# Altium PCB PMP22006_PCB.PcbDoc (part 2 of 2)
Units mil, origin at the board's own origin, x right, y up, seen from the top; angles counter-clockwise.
Board outline 2500 x 1522 mil, 4 copper layers (Top Layer, Signal Layer 1, Signal Layer 2, Bottom Layer), stack 186.034 mil thick; 52 components, 32 nets, 135 pads, 25 vias.
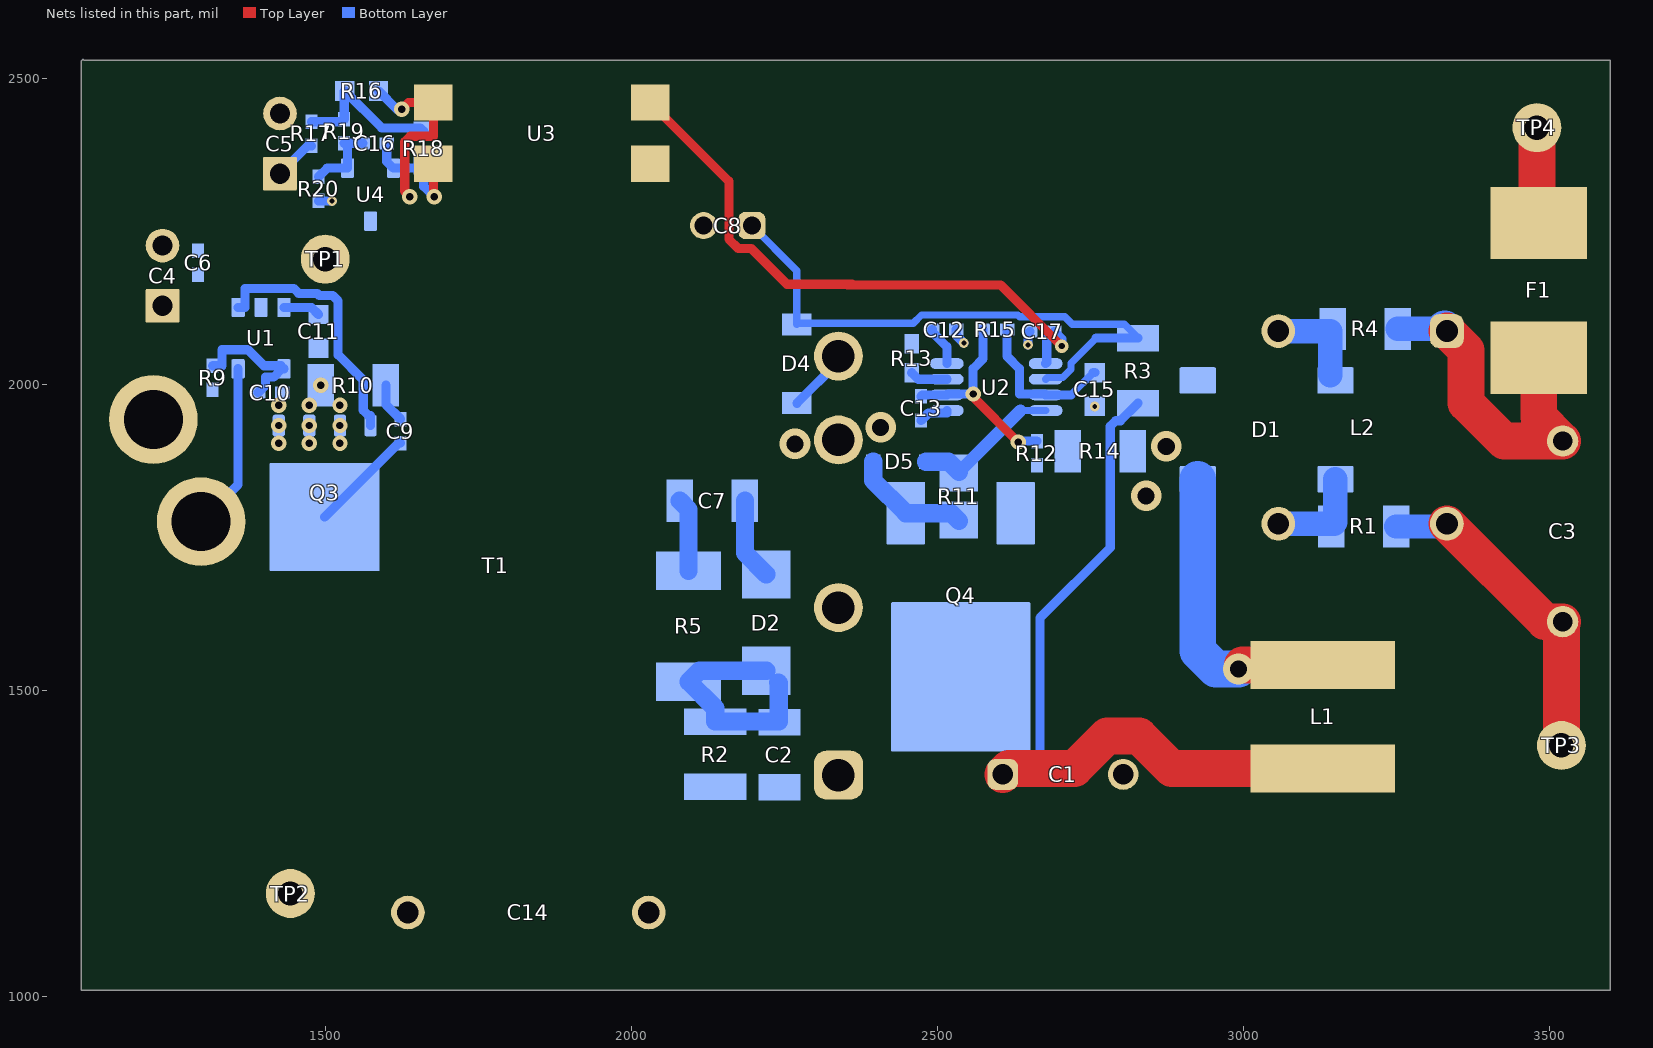
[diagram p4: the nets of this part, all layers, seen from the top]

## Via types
v1: diameter 25, hole 12, Top Layer to Bottom Layer, 15 vias
v2: diameter 50, hole 28, Top Layer to Bottom Layer, 5 vias
v3: diameter 16, hole 8, Top Layer to Bottom Layer, 4 vias
v4: diameter 22, hole 10, Top Layer to Bottom Layer, 1 vias

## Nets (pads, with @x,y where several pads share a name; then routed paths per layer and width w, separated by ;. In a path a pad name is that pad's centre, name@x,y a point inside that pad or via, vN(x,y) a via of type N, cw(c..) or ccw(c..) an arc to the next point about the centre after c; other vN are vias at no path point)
GND: C4.2 C5.2 C6.2 C10.2 C11.2 C14.1 Q3.1 Q3.2 Q3.3 R10.2 R20.1 TP2.1 U1.2 U4.3 | length 22
  Bottom Layer w15: R20.1@1488,2300.32 v3(1510,2300.32)
  other v1: 1423,1904 1473,1904 1523,1904 1423,1933.04 1473,1933.04 1523,1933.04 1423,1966 1473,1966 1523,1966 1491.85,1999
LINE: F1.2 TP4.1 | length 157
  Top Layer w60: TP4.1@3480,2420 3480,2267.24 F1.2@3483,2264.24
NetC2_2: C2.2 D2.1 R2.1 R5.2 | length 385.9
  Bottom Layer w30: D2.1@2220,1532.26 2110.81,1532.26 R5.2@2093,1514.45 2136.57,1470.87 R2.1@2136.57,1449.15 2240.57,1449.15 2240.57,1511.69 D2.1@2239.41,1512.85
NetC3_2: C3.2 F1.1 L2.1 R4.1 | length 548.6
  Top Layer w60: L2.1@3332.8,2087.48 3364,2056.28 3364,1970 3426.36,1907.64 C3.2@3522,1907.64 3483,1946.64 F1.1@3483,2043.76
  Bottom Layer w40: R4.1@3252.15,2091 L2.1@3329.28,2091
  Bottom Layer w60: L2.1@3329.28,2091 L2.1@3332.8,2087.48
NetC7_1: C7.1 R5.1 | length 120.3
  Bottom Layer w30: C7.1@2078.85,1810 2093,1795.85 R5.1@2093,1695.55
NetC7_2: C7.2 D2.2 Q4.4 T1.3 | length 134.3
  Bottom Layer w30: C7.2@2185.15,1810 2185.15,1724.59 D2.2@2219.74,1690
NetC8_1: C8.1 D4.1 R3.1 U2.2 | length 956.2
  Bottom Layer w12: C8.1@2196.37,2260 2270,2186.37 D4.1@2270,2100.33 ; D4.1@2270,2098.47 D4.1@2270,2100.33 ; U2.2@2676.71,2008.8 2679.57,2011.65 2704.83,2011.65 2718.14,2024.97 2718.14,2034.92 2759.37,2076.15 ; R3.1@2828,2076.15 2805.68,2098.47 2720.49,2098.47 2708.24,2110.72 2634.24,2110.72 2631.24,2113.72 2473.76,2113.72 2460.38,2100.33 D4.1@2270,2100.33
  Bottom Layer w15: 2759.37,2076.15 R3.1@2828,2076.15
NetC9_1: C9.1 Q3.5 Q3.6 Q3.7 Q3.8 Q3.9@1498,1783.43 T1.B U1.5 | length 449
  Bottom Layer w15: T1.B@1296,1776 1356.6,1836.6 U1.5@1356.6,2025.8 ; Q3.9@1498,1783.43 1618.88,1904.31 C9.1@1622,1904.32
NetC9_2: C9.2 R10.1 | length 65.2
  Bottom Layer w15: R10.1@1598.15,1999 1598.15,1967.54 C9.2@1622,1943.69
NetC10_1: C10.1 R9.2 U1.4 | length 221.3
  Bottom Layer w15: R9.2@1315,2030.69 1330.4,2030.69 1330.4,2056.93 1372.65,2056.93 1398.89,2030.69 1426.52,2030.69 U1.4@1431.4,2025.8 1428.12,2025.8 1414.53,2012.22 1401.5,2012.22 1401.5,1999.19 C10.1@1389.32,1987
NetC11_1: C11.1 U1.3 | length 61.4
  Bottom Layer w15: U1.3@1431.4,2126.2 1476.36,2126.2 C11.1@1488,2114.56
NetC12_2: C12.2 U2.8 | length 65.5
  Bottom Layer w15: C12.2@2491.31,2090 2491.31,2085.97 2515.29,2062 U2.8@2515.29,2034.39
NetC13_2: C13.2 R12.2 R15.1 U2.6 | length 339.1
  Top Layer w15: v1(2558.22,1984.56) 2558.22,1979.78 v1(2632,1906)
  Bottom Layer w15: C13.2@2473,1980.69 2475.52,1983.2 U2.6@2515.29,1983.2 2516.65,1984.56 v1(2558.22,1984.56) 2558.22,2026.14 2574.32,2042.23 R15.1@2574.32,2090 ; v1(2632,1906) 2633.69,1907.69 R12.2@2662.32,1907.69
NetC15_1: C15.1 R15.2 U2.3 | length 252.6
  Bottom Layer w12: 2718.2,1983.2 C15.1@2754.56,2019.56
  Bottom Layer w15: R15.2@2613.69,2090 2613.69,2046.23 2633.78,2026.14 2633.78,1984.56 2675.35,1984.56 U2.3@2676.71,1983.2 2718.2,1983.2 ; C15.1@2754.56,2019.56 C15.1@2757,2019.56
NetC16_1: C16.1 R18.2 U3.2 U4.2 | length 210.3
  Top Layer w15: U3.2@1675.83,2361 1675.83,2308.17 v1(1677,2307)
  Bottom Layer w15: C16.1@1599.68,2394.47 1599.68,2364.58 U4.2@1610.4,2353.87 1654.83,2353.87 R18.2@1660,2359.03 1660,2324 v1(1677,2307)
NetC16_2: C16.2 R19.1 R20.2 U4.1 | length 126.7
  Bottom Layer w15: R20.2@1488,2339.69 1502.18,2353.87 U4.1@1535.6,2353.87 1535.6,2388.87 R19.1@1530,2394.47 C16.2@1560.31,2394.47
NetC17_2: C17.2 U2.1 U3.4 | length 970
  Top Layer w15: U3.4@2030.17,2461 2158.85,2332.32 2158.85,2237.82 2174.19,2222.48 2195.52,2222.48 2254,2164 2360,2164 ; 2353,2163 2602.93,2163 v4(2703,2062.93)
  Bottom Layer w15: U2.1@2676.71,2034.39 2678.5,2036.18 2678.5,2074.81 ; C17.2@2690.69,2087 2703,2074.69 v4(2703,2062.93)
NetD1_1: D1.1 L1.1 | length 500.4
  Top Layer w40: v2(2992,1535) v2@2998.65,1541.65
  Top Layer w60: v2@2998.65,1541.65 L1.1@3130,1541.65
  Bottom Layer w60: D1.1@2925.4,1845.29 2925.4,1564.4 2954.8,1535 v2(2992,1535)
NetD1_2: D1.2 L2.3 R1.2 | length 164.9
  Bottom Layer w40: L2.3@3057.2,1772.52 3148.37,1772.52 3150.6,1774.75 D1.2@3150.6,1845.29
NetD1_3: D1.3 L2.2 R4.2 | length 157.6
  Bottom Layer w40: L2.2@3057.2,2087.48 3142.33,2087.48 D1.3@3142.33,2014.98
NetD4_2: D4.2 T1.6 | length 105.1
  Bottom Layer w15: D4.2@2270,1969.53 2338,2037.53 T1.6@2338,2046.5
NetD5_1: D5.1 R11.2 U2.4 | length 244.1
  Bottom Layer w12: 2635.61,1957.61 U2.4@2676.71,1957.61
  Bottom Layer w20: R11.2@2535,1857 2635.61,1957.61
  Bottom Layer w30: D5.1@2481.31,1874 2518,1874 R11.2@2535,1857
NetD5_2: D5.2 Q4.1 R11.1 | length 198.4
  Bottom Layer w30: D5.2@2394.69,1874 2394.69,1843.4 Q4.1@2448.24,1789.86 2522.14,1789.86 R11.1@2535,1777
NetQ3_4: Q3.4 U1.1 | length 430.4
  Bottom Layer w15: U1.1@1356.6,2126.2 1367.8,2126.2 1367.8,2157.32 1447.45,2157.32 1455.7,2149.07 1485.84,2149.07 1489.23,2145.68 1511.1,2145.68 1520.11,2136.68 1520.11,2048.59 1561.12,2007.57 1561.12,1958.18 1570.13,1949.18 1573,1949.18 Q3.4@1573,1933.04
NetQ4_3: Q4.3 R12.1 R14.1
NetR13_2: R13.2 U2.7 | length 61.7
  Bottom Layer w15: R13.2@2458,2019.38 2468.58,2008.8 U2.7@2515.29,2008.8
NetR16_1: R16.1 U3.1 | length 311.5
  Top Layer w15: v1(1624,2450) 1635,2461 U3.1@1675.83,2461 1675.83,2405.9 1637.97,2405.9 1628.96,2396.9 1628.96,2316.1 1637,2308.06 v1(1637,2307.03) v1@1637,2306
  Bottom Layer w15: R16.1@1586.19,2480 1616.19,2450 v1(1624,2450) ; v1@1633.47,2310.56 v1(1637,2307.03)
NetR16_2: R16.2 R17.1 R18.1 R19.2 | length 258.2
  Bottom Layer w15: R17.1@1476.36,2429.68 1525.85,2429.68 R19.2@1530,2433.84 1530,2478.93 R16.2@1531.07,2480 1591.39,2419.68 1654.47,2419.68 R18.1@1660,2414.15
NTRL: C3.1 L2.4 R1.1 TP3.1 | length 543.3
  Top Layer w60: L2.4@3332.8,1772.52 3492.95,1612.36 C3.1@3522,1612.36 3520,1610.36 TP3.1@3520,1410
  Bottom Layer w40: R1.1@3250.15,1768 3328.28,1768 L2.4@3332.8,1772.52
PGND: C1.2 C8.2 C12.1 C13.1 C14.2 C15.2 C17.1 D1.4 R13.1 R14.2 T1.5 U2.5 U3.3 | length 101.9
  Bottom Layer w15: C13.1@2473,1941.32 2485.19,1953.5 2515.29,1953.5 U2.5@2515.29,1957.61 ; C12.1@2530.68,2090 2530.68,2080.32 v3(2543,2068) ; v3(2648,2065) 2648,2083.68 C17.1@2651.32,2087
  other v2: 2841,1818 2874,1899 2267,1903 2407,1930
  other v3: 2757,1963.95
VIN: C1.1 C2.1 L1.2 R2.2 R3.2 T1.1 | length 1297.7
  Top Layer w60: C1.1@2606.57,1362.67 2616.26,1372.35 2724.05,1372.35 2777.34,1425.64 2829.51,1425.64 2882.8,1372.35 L1.2@3130,1372.35
  Bottom Layer w15: C1.1@2606.57,1362.67 2628.63,1384.72 2667.55,1384.72 2667.55,1618.55 2782.44,1733.44 2782.44,1931.82 2791.44,1940.82 2798.97,1940.82 R3.2@2828,1969.85
VOUT: C4.1 C5.1 C6.1 R9.1 R17.2 T1.A TP1.1 | length 82.5
  Bottom Layer w15: C5.1@1437.29,2344.79 C5.1@1425,2344.79 1470.53,2390.31 R17.2@1476.36,2390.31
pads on no net: Q3.9@1440.91,1767.88 Q3.9@1440.91,1837.96 Q3.9@1498,1767.88 Q3.9@1498,1801.35 Q3.9@1498,1837.96 Q3.9@1555.09,1767.88 Q3.9@1555.09,1837.96

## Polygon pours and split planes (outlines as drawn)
VIN on Bottom Layer "BOTTOM_LAYER_VIN_P000" (solid, remove dead copper, pour order 0): 2054,1236 2054,1580.46 2384,1580.46 2384,1375 2398,1361 2404,1367 2530,1367 2530,1401.94 2538.06,1410 2733,1410 2733,1312 2702,1281 2387,1281 2387,1236 2384,1233 2382.39,1234.61 2043.23,1234.61
NetC7_2 on Bottom Layer "BOTTOM_LAYER_NETC7_2_P002" (solid, remove dead copper, pour order 2): 2405,1391 2653.34,1391 2662.3,1399.96 2662.3,1715.06 2283.06,1715.06 2281,1713 2264,1730 2264,1758 2171,1758 2163,1750 2163,1590 2399.67,1590 2401.67,1592 2406,1587.67 2406,1393
NetQ4_3 on Bottom Layer "BOTTOM_LAYER_NETQ4_3_P004" (solid, remove dead copper, pour order 4): 2590,1727 2590,1855 2585,1860 2636,1860 2636,1884 2642,1890 2682,1890 2682,1936 2684,1938 2761,1938 2761,1728 2762,1727 2761,1726 2591,1726
PGND on Bottom Layer "BOTTOM_LAYER_PGND_P012" (solid, remove dead copper, pour order 12): 2059,1295 2961,1295 2959,1297 2959,2163 2332,2163 2268,2227 2233.66,2305.66 2191,2334 2114,2411 1951,2411 1951,1075 1954,1072 2069,1072 2069,1294 2066,1297
NetC9_1 on Bottom Layer "BOTTOM_LAYER_NETC9_1_P006" (solid, remove dead copper, pour order 6): 1600,1680 1245,1680 1245,1706 1247,1708 1185,1770 1185,1844 1210,1869 1353,1869 1361,1877 1603,1877 1603,1681 1601,1679
VOUT on Bottom Layer "BOTTOM_LAYER_VOUT_P008" (solid, remove dead copper, pour order 8): 1112,1867 1112,2176 1108,2180 1234.89,2279.04 1338,2349 1358,2369 1566,2369 1566,2130 1542,2106 1336,2106 1336,1872 1331,1867
GND on Bottom Layer "BOTTOM_LAYER_GND_P024" (solid, remove dead copper, pour order 24): 1286,2508 1764.61,2508 1767,2510.39 1767,1009 1335.56,1009 1326.56,1000 1102,1000 1102,2527 1120,2509 1287,2509
VOUT on Top Layer "TOP_LAYER_VOUT_P010" (solid, remove dead copper, pour order 10): 1112,1867 1112,2176 1108,2180 1234.89,2279.04 1338,2349 1358,2369 1566,2369 1566,2130 1542,2106 1336,2106 1336,1872 1331,1867
PGND on Top Layer "TOP_LAYER_PGND_P020" (solid, remove dead copper, pour order 20): 2052,1311 2959,1311 2959,2165 2330,2165 2268,2227 2268,2334 2191,2334 2114,2411 1951,2411 1951,1075 1954,1072 2069,1072 2069,1294
GND on Top Layer "TOP_LAYER_GND_P022" (solid, remove dead copper, pour order 22): 1675,1033 1675,1192 1542,1192 1542,2203 1726,2203 1726,2524 1728,2526 1722,2532 1103,2532 1103,1009 1104,1010 1676,1010 1676,1033
PGND on Signal Layer 1 "SIGNAL_LAYER_1_PGND_P014" (solid, remove dead copper, pour order 14): 2059,1295 2961,1295 2959,1297 2959,2163 2332,2163 2268,2227 2233.66,2305.66 2191,2334 2114,2411 1951,2411 1951,1075 1954,1072 2069,1072 2069,1294 2066,1297
GND on Signal Layer 1 "SIGNAL_LAYER_1_GND_P026" (solid, remove dead copper, pour order 26): 1286,2508 1764.61,2508 1767,2510.39 1767,1009 1335.56,1009 1326.56,1000 1102,1000 1102,2527 1120,2509 1287,2509
PGND on Signal Layer 2 "SIGNAL_LAYER_2_PGND_P018" (solid, remove dead copper, pour order 18): 2059,1295 2961,1295 2959,1297 2959,2161 2334,2161 2268,2227 2233.66,2305.66 2191,2334 2114,2411 1951,2411 1951,1075 1954,1072 2069,1072 2069,1294 2066,1297
GND on Signal Layer 2 "SIGNAL_LAYER_2_GND_P028" (solid, remove dead copper, pour order 28): 1286,2508 1764.61,2508 1767,2510.39 1767,1009 1335.56,1009 1326.56,1000 1102,1000 1102,2527 1120,2509 1287,2509

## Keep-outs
Keep-Out Layer:
  text ".Layer_Name" at 577,-858.49 h60

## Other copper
Top Layer:
  text ".Layer_Name" at 577,-858.49 h60
Bottom Layer:
  text ".Layer_Name" at 577,-858.49 h60

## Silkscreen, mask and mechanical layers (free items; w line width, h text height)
Top Overlay:
  text "'.PRJ_Number'.PCB_Rev-" at 2578,1181 h108.27
  text ".Layer_Name" at 577,-858.49 h60
Bottom Overlay:
  text ".Layer_Name" at 577,-858.49 h60
Top Paste:
  text ".Layer_Name" at 577,-858.49 h60
Bottom Paste:
  text ".Layer_Name" at 577,-858.49 h60
Top Solder:
  text ".Layer_Name" at 577,-858.49 h60
  text ".Layer_Name" at 577,-858.49 h60
Bottom Solder:
  text ".Layer_Name" at 577,-858.49 h60
Drill Guide:
  text ".Layer_Name" at 577,-858.49 h60
M1 Board Outline:
  text ".Layer_Name" at 577,-858.49 h60
M2 Board Dimensions:
  rectangle: 125,-400 500,-275
  rectangle: 0,-275 125,-150
  lines w7: 0,-275 1000,-275 ; 125,-400 125,-150 ; 250,-400 250,-150 ; 500,-400 500,-150 ; 750,-400 750,-150 ; 0,-400 0,-150 1000,-150 1000,-400 0,-400
  text ".Layer_Name" at 577,-858.49 h60
M3 3D STEP Top:
  text ".Layer_Name" at 577,-858.49 h60
M4 3D STEP Bottom:
  text ".Layer_Name" at 577,-858.49 h60
M5 Assembly Top:
  lines w10: -292,-930.17 6308,-930.17 ; -292,-726.83 6310,-726.83 ; -292,-523.5 -292,-1133.5 3713,-1133.5 6310,-1133.5 6310,-523.5 -291.5,-523.5 -291.5,-1133.5 1284,-1133.5 ; 2173,-1133.5 2173,-523.5 ; 3440,-726.83 3440,-523.5 ; 4280,-726.83 4280,-523.5 ; 4902,-1140 4902,-937.17
  text "COMPONENTS MARKED 'DNP' SHOULD NOT BE POPULATED." at 1153.5,-318.5 h60
  text "ASSEMBLY VARIANT:" at 1153,-434 h60
  text ".VariantName" at 2189,-434 h60
  text "PCB VIEWED FROM TOP SIDE" at -228.5,-655.67 h60
  text "BOARD #:" at 2248,-655.67 h60
  text ".PRJ_Number" at 2793.5,-655.67 h60
  text "REV:" at 3638,-655.67 h60
  text ".PCB_Rev" at 3929.5,-655.67 h60
  text "SVN REV:" at 4476,-655.67 h60
  text ".VersionControl_RevNumber" at 4982,-655.67 h60
  text "TID #:" at 2248,-859 h60
  text ".TID" at 2793.5,-859 h60
  text "PLOT NAME =" at -228.5,-1064.34 h60
  text ".plot_File_Name" at 577,-1064.34 h60
  text "GENERATED    :" at 2250,-1064.34 h60
  text ".Print_Date" at 3119.5,-1064.34 h60
  text ".Print_Time" at 3848.5,-1064.34 h60
  text "TEXAS INSTRUMENTS" at 5113,-1064.34 h60
M6 Assembly Bottom:
  lines w10: -292.5,-727.33 6309.5,-727.33 ; -290.5,-930.67 6309.5,-930.67 ; 1115.5,-1140.5 1115.5,-937.67 ; 1737.5,-727.33 1737.5,-524 ; 2577.5,-727.33 2577.5,-524 ; 3844.5,-1134 3844.5,-524 ; 4733.5,-1134 6309,-1134 6309,-524 -292.5,-524 -292.5,-1134 2304.5,-1134 6309.5,-1134 6309.5,-524
  text "COMPONENTS MARKED 'DNP' SHOULD NOT BE POPULATED." at 6102,-318 h60
  text ".VariantName" at 5058,-434 h60
  text "ASSEMBLY VARIANT:" at 6097,-434 h60
  text ".VersionControl_RevNumber" at 1035.5,-656.17 h60
  text "SVN REV:" at 1541.5,-656.17 h60
  text ".PCB_Rev" at 2088,-656.17 h60
  text "REV:" at 2379.5,-656.17 h60
  text ".PRJ_Number" at 3224,-656.17 h60
  text "BOARD #:" at 3769.5,-656.17 h60
  text "PCB VIEWED FROM BOTTOM SIDE" at 6246,-656.17 h60
  text ".TID" at 3224,-859.5 h60
  text "TID #:" at 3769.5,-859.5 h60
  text "TEXAS INSTRUMENTS" at 904.5,-1064.84 h60
  text ".Print_Time" at 2169,-1064.84 h60
  text ".Print_Date" at 2898,-1064.84 h60
  text "GENERATED    :" at 3767.5,-1064.84 h60
  text ".plot_File_Name" at 5440.5,-1064.84 h60
  text "PLOT NAME =" at 6246,-1064.84 h60
M9 Title Sheet:
  drawing of 57 lines, arcs and shapes, not listed
  text "1" at 739.84,8036.5 h70
  text "2" at 3235.5,8036.5 h70
  text "3" at 5724.84,8036.5 h70
  text "4" at 8231.51,8036.5 h70
  text "5" at 10730.5,8036.5 h70
  text "6" at 13235.5,8036.5 h70
  text "A" at -416.5,6893.5 h70
  text "A" at 14383.5,6893.5 h70
  text "B" at -416.5,4513.5 h70
  text "B" at 14383.5,4513.5 h70
  text "C" at -416.5,2138.5 h70
  text "C" at 14383.5,2138.5 h70
  text "PROJECT TITLE:" at 11343.5,277.5 h45
  text ".PRJ_Title" at 11393.5,144.17 h70
  text "DESIGNED FOR:" at 11343.5,-23.5 h45
  text ".PRJ_Customer" at 11393.5,-163.5 h70
  text "D" at -416.5,-231.5 h70
  text "D" at 14383.5,-231.5 h70
  text "FILE NAME:" at 11343.5,-323.5 h45
  text ".PCB_File_Name_No_Path" at 11393.5,-443.5 h70
  text "Texas Instruments (TI) and/or its licensors do not warrant the accuracy or completeness of this specification" at 6374,-605.34 h45
  text "ENGINEER:" at 11343.5,-613.5 h45
  text "LAYOUT BY:" at 12848.5,-613.5 h45
  text "or any information contained therein. TI and/or its licensors do not warrant that this design will meet" at 6329.01,-718 h45
  text ".PRJ_Engineer" at 11393.5,-768.49 h70
  text ".PCB_Layout" at 12899,-768.49 h70
  text "the specifications, will be suitable for your application or fit for any particular purpose, or will operate in" at 6329.01,-830.67 h45
  text ".Layer_Name" at 577,-858.49 h60
  text "ALTIUM DESIGNER VERSION:" at 12848.5,-923.5 h45
  text "an implementation. TI and/or its licensors do not warrant that the design is production worthy. You should" at 6329.01,-943.33 h45
  text "completely validate and test your design implementation to confirm the system functionality for your application." at 6374,-1056 h45
  text ".print_Scale" at 11393.5,-1056.83 h70
  text ".Application_BuildNumber" at 12899,-1056.83 h70
  text "1" at 739.84,-1263.5 h70
  text "2" at 3235.5,-1263.5 h70
  text "3" at 5724.84,-1263.5 h70
  text "4" at 8231.51,-1263.5 h70
  text "5" at 10730.5,-1263.5 h70
  text "6" at 13235.5,-1263.5 h70
M10 Fab Notes:
  drawing of 173 lines, arcs and shapes, not listed
  text "DESIGN INFORMATION" at 12378.02,6201 h60
  text "MIN. TRACK WIDTH:" at 11733.46,6021 h60
  text "8" at 12829.7,6021 h60
  text "MIL" at 12984.46,6021 h60
  text "MIN. CLEARANCE:" at 11733.46,5889 h60
  text "0.2" at 12769.7,5889 h60
  text "mm" at 12984.46,5889 h60
  text "MIN. VIA PAD SIZE:" at 11733.46,5757 h60
  text "24" at 12799.71,5757 h60
  text "MIL" at 12984.46,5757 h60
  text "0.05mm (2MIL)" at 12428.46,5615.29 h60
  text "MINIMUM ANNULAR RING" at 11404.23,5611 h60
  text "EXTERNAL" at 13136.46,5611 h60
  text "PER" at 11604.23,5493 h60
  text "IPC-D-275 CLASS 2 LEVEL C" at 11824.23,5493 h60
  text "MIL, HOLES" at 13312.46,5380.71 h60
  text "+/-" at 12920,5380 h60
  text "+/-" at 13774,5380 h60
  text "REGISTRATION TOLERANCES:" at 11404.23,5375 h60
  text "METAL" at 12604,5375 h60
  text "5" at 13180.2,5375 h60
  text "3" at 14013.2,5375 h60
  text "MIL" at 14129.46,5375 h60
  text "+/-" at 13774,5262 h60
  text "HOLE SIZE TOLERANCE (UNLESS OTHERWISE SPECIFIED):" at 11404.23,5257 h60
  text "3" at 14013.2,5257 h60
  text "MIL" at 14129.46,5257 h60
  text "MATERIAL:" at 11329.46,5047.54 h60
  text "FR-4 High Tg" at 12315.9,4907.21 h60
  text "FR-408" at 11750.46,4898.64 h60
  text "OTHER" at 13238.46,4898.64 h60
  text "X" at 12161,4895 h60
  text "62 MIL (1.6mm) +/-10%" at 12070.56,4735.92 h60
  text "THICKNESS:" at 11404.23,4731.64 h60
  text "X" at 11942.4,4731.64 h60
  text "OTHER" at 13355.46,4731.64 h60
  text "TOLERANCE:" at 11404.23,4573.64 h60
  text "X" at 12243.53,4573.64 h60
  text "ANSI IPC-6012 TYPE 3 CLASS 2" at 12430.48,4573.64 h60
  text "OTHER +/-" at 12430.46,4417.64 h60
  text "BOW & TWIST:" at 11404.23,4260.64 h60
  text "X" at 12243.53,4260.64 h60
  text "ANSI IPC-6012 TYPE 3 CLASS 2" at 12430.48,4260.64 h60
  text "OTHER +/-" at 12430.46,4102.13 h60
  text "DRILLING:" at 11329.46,3963.64 h60
  text "REFERENCE:" at 11404.23,3846.64 h60
  text "X" at 12052.46,3846.64 h60
  text "AS SHOWN" at 12239.46,3846.64 h60
  text "X" at 12953.46,3846.64 h60
  text "NC_DRILL FILES" at 13090.46,3846.64 h60
  text "PTH COPPER THICKNESS:" at 11404.23,3688.64 h60
  text "X" at 12534.46,3688.64 h60
  text "20-30 um" at 12671.46,3688.64 h60
  text "OTHER" at 13388.46,3688.64 h60
  text "BOARD FINISH:" at 11329.46,3529.64 h60
  text "SILKSCREEN:" at 11484.68,3411.64 h60
  text "X" at 12433.46,3411.64 h60
  text "TOP" at 12559.46,3411.64 h60
  text "X" at 12943.46,3411.64 h60
  text "BOTTOM" at 13070.46,3411.64 h60
  text "SILKSCREEN COLOR:" at 11484.68,3244.64 h60
  text "X" at 12432.42,3244.64 h60
  text "WHITE" at 12559.46,3244.64 h60
  text "OTHER" at 13070.46,3244.64 h60
  text "X" at 12563.42,3085.44 h60
  text "GREEN" at 12690.46,3085.44 h60
  text "OTHER" at 13308.46,3085.44 h60
  text "SOLDER RESIST COLOR:" at 11484.68,3074.64 h60
  text "X" at 12563.42,2915.44 h60
  text "MATTE" at 12690.46,2915.44 h60
  text "SEMI-GLOSS" at 13308,2914.8 h60
  text "IMMERSION GOLD (ENIG)" at 12390.46,2726.92 h60
  text "ENEPIG" at 13728,2723.64 h60
  text "SURFACE FINISH:" at 11329.46,2722.64 h60
  text "X" at 12203.51,2722.64 h60
  text "IMM. TIN/SILVER OR EQUIV" at 11659,2565.64 h60
  text "OTHER" at 13090.46,2565.64 h60
  text "ARRAY/PANEL:" at 11329.46,2386.64 h60
  text "CUT AND TRIM PER M1 BOARD OUTLINE" at 12390.46,2382.35 h60
  text "N.C. ROUTE" at 12390.46,2230.64 h60
  text "X" at 13069.46,2230.64 h60
  text "V. SCORE" at 13256.46,2230.64 h60
  text "CERTIFICATION:" at 11329.46,2093.64 h60
  text "MATERIALS AND WORKMANSHIP FOR ALL PCBS" at 12054.46,2093.64 h60
  text "TO MEET OR EXCEED THE REQUIREMENTS OF:" at 12054.46,1995.64 h60
  text "X" at 11680.96,1859.13 h60
  text "ANSI IPC-A-600F CLASS ->" at 11819.96,1859.13 h60
  text "X" at 13459.02,1859.13 h60
  text "2" at 13577.96,1859.14 h60
  text "1" at 13262.96,1857.64 h60
  text "3" at 13931.96,1857.64 h60
  text "X" at 12495.02,1699.64 h60
  text "RoHS" at 12631.96,1699.64 h60
  text "OTHER" at 13276.36,1699.64 h60
  text "PER ORDER" at 13673.42,1699.64 h60
  text "ALL BOARDS MUST MEET OR EXCEED UL94-V0 REQUIREMENTS." at 11357,1534 h60
  text "PCB MUST BEAR THE UL94V-0 UL REGISTERED MATERIAL ID NUMBER" at 11357,1414 h60
  text "ADDITIONAL REQUIREMENTS:" at 11329.46,1240.64 h60
  text "MICROSECTION:" at 11404.23,1125.64 h60
  text "YES" at 12309.96,1125.64 h60
  text "REQUIRED" at 13171.46,969.49 h60
  text "BARE BOARD ELEC. TEST:" at 11404.23,966.64 h60
  text "NONE" at 12709.96,966.64 h60
  text "X" at 13044.46,966.64 h60
  text "PER ORDER" at 13763.46,966.64 h60
  text ".Layer_Name" at 577,-858.49 h60
M11 Gerber Information:
  lines w10: -292,-930.17 6308,-930.17 ; -292,-726.83 6310,-726.83 ; -292,-523.5 -292,-1133.5 3713,-1133.5 6310,-1133.5 6310,-523.5 -291.5,-523.5 -291.5,-1133.5 1284,-1133.5 ; 2173,-1133.5 2173,-523.5 ; 3440,-726.83 3440,-523.5 ; 4280,-726.83 4280,-523.5 ; 4902,-1140 4902,-937.17
  text "ALL ARTWORK VIEWED FROM TOP SIDE" at -228.5,-655.67 h60
  text "BOARD #:" at 2248,-655.67 h60
  text ".PRJ_Number" at 2793.5,-655.67 h60
  text "REV:" at 3638,-655.67 h60
  text ".PCB_Rev" at 3929.5,-655.67 h60
  text "SVN REV:" at 4476,-655.67 h60
  text ".VersionControl_RevNumber" at 4982,-655.67 h60
  text "LAYER NAME =" at -228.5,-858.49 h60
  text "TID #:" at 2248,-859 h60
  text ".TID" at 2793.5,-859 h60
  text "PLOT NAME =" at -228.5,-1064.34 h60
  text ".plot_File_Name" at 577,-1064.34 h60
  text "GENERATED    :" at 2250,-1064.34 h60
  text ".Print_Date" at 3119.5,-1064.34 h60
  text ".Print_Time" at 3848.5,-1064.34 h60
  text "TEXAS INSTRUMENTS" at 5113,-1064.34 h60
M12 Stackup:
  drawing of 527 lines, arcs and shapes, not listed
  text "Layer" at 9797.84,7785 h60
  text "Name" at 10207.76,7785 h60
  text "Material" at 11147.5,7785 h60
  text "Thickness" at 12007.26,7785 h60
  text "Constant" at 12657.1,7785 h60
  text "Board Layer Stack" at 13226.96,7785 h60
  text "Board Layer Stack" at 14346.64,7785 h60
  text "1" at 9797.84,7665 h60
  text "Top Overlay" at 10207.76,7665 h60
  text "2" at 9797.84,7545 h60
  text "Top Solder" at 10207.76,7545 h60
  text "Solder Resist" at 11147.5,7545 h60
  text "0.40mil" at 12007.26,7545 h60
  text "3.5" at 12657.1,7545 h60
  text "3" at 9797.84,7425 h60
  text "Top Layer" at 10207.76,7425 h60
  text "Copper" at 11147.5,7425 h60
  text "2.80mil" at 12007.26,7425 h60
  text "4" at 9797.84,7305 h60
  text "Dielectric1" at 10207.76,7305 h60
  text "FR-4" at 11147.5,7305 h60
  text "59.20mil" at 12007.26,7305 h60
  text "4.8" at 12657.1,7305 h60
  text "5" at 9797.84,7185 h60
  text "Signal Layer 1" at 10207.76,7185 h60
  text "Copper" at 11147.5,7185 h60
  text "1.42mil" at 12007.26,7185 h60
  text "6" at 9797.84,7065 h60
  text "Dielectric 2" at 10207.76,7065 h60
  text "FR-4" at 11147.5,7065 h60
  text "59.20mil" at 12007.26,7065 h60
  text "4.8" at 12657.1,7065 h60
  text "7" at 9797.84,6945 h60
  text "Signal Layer 2" at 10207.76,6945 h60
  text "Copper" at 11147.5,6945 h60
  text "1.42mil" at 12007.26,6945 h60
  text "8" at 9797.84,6825 h60
  text "Dielectric 3" at 10207.76,6825 h60
  text "FR-4" at 11147.5,6825 h60
  text "59.20mil" at 12007.26,6825 h60
  text "4.8" at 12657.1,6825 h60
  text "9" at 9797.84,6705 h60
  text "Bottom Layer" at 10207.76,6705 h60
  text "Copper" at 11147.5,6705 h60
  text "2.80mil" at 12007.26,6705 h60
  text "10" at 9797.84,6585 h60
  text "Bottom Solder" at 10207.76,6585 h60
  text "Solder Resist" at 11147.5,6585 h60
  text "0.40mil" at 12007.26,6585 h60
  text "3.5" at 12657.1,6585 h60
  text "11" at 9797.84,6465 h60
  text "Bottom Overlay" at 10207.76,6465 h60
  text ".Layer_Name" at 577,-858.49 h60
M13 Component Bodies Top:
  text ".Layer_Name" at 577,-858.49 h60
M14 Component Bodies Bottom:
  text ".Layer_Name" at 577,-858.49 h60
M15 Courtyards Top:
  text ".Layer_Name" at 577,-858.49 h60
M16 Courtyards Bottom:
  text ".Layer_Name" at 577,-858.49 h60
Drill Drawing:
  text ".Layer_Name" at 577,-858.49 h60
M17 Embedded Cavity:
  text ".Layer_Name" at 577,-858.49 h60
M18 Embedded Assembly:
  text ".Layer_Name" at 577,-858.49 h60
M19 Embedded Keepout:
  text ".Layer_Name" at 577,-858.49 h60

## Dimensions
0,-400 to 1000,-400 on M2 Board Dimensions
